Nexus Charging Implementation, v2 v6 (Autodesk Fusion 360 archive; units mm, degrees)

design "Nexus Charging Implementation, v2" references "9401-0-15-15-23-27-10-0 - Connector One", "0436-0-15-15-03-27-10-0 - Connector Two v2"
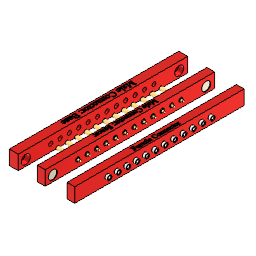
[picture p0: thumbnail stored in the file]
description: STEP AP214
part number: mill-max-0855
base_feature "Base Feature1" bodies "Pin 1"
copy_paste_bodies "CopyPasteBodies1" bodies "Pin Cover"
move "Move1"
sketch "Sketch1" plane through (0, 0, 0) normal (1, 0, 0) x axis (0, 1, 0)
  line L1 (-2.1437, -2.54) -> (6.35, -2.54)
  line L2 (-2.1437, 2.4142) -> (-2.1437, -2.54)
  line L3 (6.35, 2.4142) -> (-2.1437, 2.4142)
  line L4 (6.35, -2.54) -> (6.35, 2.4142)
  circle C1 centre (0, 0) radius 1.27
  circle C2 centre (0, 0) radius 1.27
  circle C3 centre (0, 0) radius 1.5151
  point P1 (0, 0)
  point P6 (0, 0)
  point P8 (0, 0)
  horizontal L1
  vertical L2
  horizontal L3
  vertical L4
  coincident P1 P6
  concentric C1 C2
  coincident P1 P8
extrude "Extrude1" new body sketch "Sketch1" profile of C1 C2 C3 against normal blind 4.826 and along normal blind 1.524 bodies "Pin Cover 1", "Pin Cover"
extrude "Extrude2" new body sketch "Sketch1" profile of L1 L2 L3 L4 C3 along normal blind 1.27 bodies "Connecting Pins", "Pin Cover"
copy_paste_bodies "CopyPasteBodies2" bodies "Pin Cover"
move "Move2"
move "Move3"
sketch "Circle Magnet" plane through (0, 0, 0) normal (1, 0, 0) x axis (0, 1, 0)
  circle C1 centre (0, 0) radius 3.175
  point P1 (0, 0)
  point P2 (0, 0)
  coincident P1 P2
  dimension "d7" diameter C1 = 6.35
extrude "Extrude3" new body sketch "Circle Magnet" along normal blind 3.175 bodies "Magnet", "Pin Cover"
move "Move4"
copy_paste_bodies "CopyPasteBodies3" bodies "Pin Cover"
move "Move5"
copy_paste_bodies "CopyPasteBodies4" bodies "Pin Cover"
copy_paste_bodies "CopyPasteBodies5" bodies "Pin Cover"
move "Move6"
move "Move7"
copy_paste_bodies "CopyPasteBodies6"
move "Move8"
copy_paste_bodies "CopyPasteBodies7"
move "Move9"
copy_paste_bodies "CopyPasteBodies8"
move "Move10"
copy_paste_bodies "CopyPasteBodies9"
move "Move11"
move_face "MoveFace1"
move_face "MoveFace2"
move_face "MoveFace3"
move "Move12"
copy_paste_bodies "CopyPasteBodies10" bodies "Pin Cover"
move "Move13"
move "Move14"
move "Move15"
move "Move16"
move_face "MoveFace4"
move "Move17"
extrude "Extrude4" new body of existing geometry blind 69.85 bodies "Pin Cover"
sketch "Sketch3" plane through (0, 0, 0) normal (1, 0, 0) x axis (0, 1, 0)
sketch "Sketch4" plane through (0, 0, 0) normal (1, 0, 0) x axis (0, 1, 0)
  line L1 (-5.08, 5.08) -> (76.2, 5.08)
  line L2 (-5.08, -5.08) -> (-5.08, 5.08)
  line L3 (76.2, -5.08) -> (-5.08, -5.08)
  line L4 (76.2, 5.08) -> (76.2, -5.08)
  circle C1 centre (72.644, 0) radius 1.3746
  circle C2 centre (66.04, 0) radius 1.3678
  circle C3 centre (59.436, 0) radius 1.4235
  circle C4 centre (52.832, 0) radius 1.4502
  circle C5 centre (46.228, 0) radius 1.4235
  circle C6 centre (26.416, 0) radius 1.4235
  circle C7 centre (39.624, 0) radius 1.4235
  circle C8 centre (0, 0) radius 1.4502
  circle C9 centre (6.604, 0) radius 1.4235
  circle C10 centre (13.208, 0) radius 1.4235
  circle C11 centre (19.812, 0) radius 1.4502
  circle C12 centre (26.416, 0) radius 1.4235
  circle C13 centre (33.02, 0) radius 1.3678
  horizontal L1
  vertical L2
  horizontal L3
  vertical L4
extrude "Extrude5" new body sketch "Sketch4" against normal blind 7.62 bodies "Connector Big", "Pin Cover"
move "Move18"
extrude "Extrude6" cut of existing geometry blind -0.508
extrude "Extrude7" cut of existing geometry blind -1.016
extrude "Extrude8" new body of existing geometry blind 0.254 bodies "Connector Big Partial", "Pin Cover"
extrude "Extrude9" add of existing geometry blind 6.35 bodies "Connector Big Partial"
extrude "Extrude10" of existing geometry blind 10.16
extrude "Extrude11" new body of existing geometry blind 11.43 bodies "Pin Cover"
extrude "Extrude12" cut of existing geometry blind 2.54
extrude "Extrude13" cut of existing geometry blind -2.54
extrude "Extrude14" cut of existing geometry blind -1.016
extrude "Extrude15" add of existing geometry blind 0.762
copy_paste_bodies "CopyPasteBodies11" bodies "Pin Cover"
move "Move19"
extrude "Extrude16" add of existing geometry blind 8.89
extrude "Extrude17" add of existing geometry blind 0.254
extrude "Extrude18" add of existing geometry blind 0.254
component_insert "Component Insert1"
component_insert "Component Insert2"
copy_paste_bodies "CopyPasteBodies12" bodies "Pin Cover"
move "Move20"
position "Position1"
sketch "Sketch5" plane through (30.5751, 0, 0) normal (-1, 0, 0) x axis (0, -1, 0)
  circle C1 centre (0, 0) radius 1.016
  circle C2 centre (0, 0) radius 1.591
  concentric C1 C2
sketch "Sketch6" plane through (30.5751, 0, 0) normal (-1, 0, 0) x axis (0, -1, 0)
sketch "Female Charging Contact Sketch" plane through (30.5751, 0, 0) normal (-1, 0, 0) x axis (0, -1, 0)
  circle C1 centre (0, 0) radius 1.016
  circle C2 centre (0, 0) radius 1.2701
  circle C3 centre (0, 0) radius 1.754
  point P1 (0, 0)
  point P3 (0, 0)
  coincident P1 P3
  concentric C1 C3
extrude "Extrude19" new body sketch "Female Charging Contact Sketch" profile of C2 C3 against normal blind 5.588 bodies "Female Connector Spacer 1", "Pin Cover"
extrude "Extrude20" cut of existing geometry blind -2.54
extrude "Extrude21" add of existing geometry blind 1.27
move "Move21"
extrude "Extrude22" cut of existing geometry blind -2.1844
position "Position2"
component_insert "Component Insert3" bodies "Pin Cover"
copy_paste_bodies "CopyPasteBodies13"
move "Move22"
copy_paste_bodies "CopyPasteBodies14"
move "Move23"
copy_paste_bodies "CopyPasteBodies15"
move "Move24"
copy_paste_bodies "CopyPasteBodies16"
move "Move25"
component_insert "Component Insert4" bodies "Pin Cover"
component_insert "Component Insert6" bodies "Pin Cover"
component_insert "Component Insert7" bodies "Pin Cover"
component_insert "Component Insert8" bodies "Pin Cover"
component_insert "Component Insert9" bodies "Pin Cover"
component_insert "Component Insert10" bodies "Pin Cover"
component_insert "Component Insert11" bodies "Pin Cover"
component_insert "Component Insert12" bodies "Pin Cover"
component_insert "Component Insert13" bodies "Pin Cover"
position "Position3"
component_insert "Component Insert14" bodies "Pin Cover"
copy_paste_bodies "CopyPasteBodies17"
move "Move26"
extrude "Extrude23" add of existing geometry blind 1.3462
extrude "Extrude24" add of existing geometry blind 0.1524 bodies "Connector Big Female End (1)", "Female Connector Spacer 2", "Female Connector Spacer 3", "Female Connector Spacer 6", "Female Connector Spacer 5", "Female Connector Spacer 4", "Female Connector Spacer 7", "Female Connector Spacer 8"
sketch "Sketch8" plane through (7.7978, 0, 0) normal (1, 0, 0) x axis (0, 1, 0)
  line L1 (-22.86, 5.08) -> (96.52, 5.08)
  line L2 (-22.86, -5.08) -> (-22.86, 5.08)
  line L3 (85.09, -5.08) -> (-22.86, -5.08)
  line L4 (96.52, -5.08) -> (85.09, -5.08)
  line L5 (96.52, 5.08) -> (96.52, -5.08)
  circle C1 centre (0, 0) radius 1.4502
  circle C2 centre (13.208, 0) radius 1.4235
  circle C3 centre (33.02, 0) radius 1.3678
  circle C4 centre (19.812, 0) radius 1.4502
  circle C5 centre (39.624, 0) radius 1.4235
  circle C6 centre (26.416, 0) radius 1.4235
  circle C7 centre (59.436, 0) radius 1.4235
  circle C8 centre (66.04, 0) radius 1.3678
  circle C9 centre (6.604, 0) radius 1.4235
  circle C10 centre (52.832, 0) radius 1.4502
  circle C11 centre (72.644, 0) radius 1.3746
  circle C12 centre (46.228, 0) radius 1.4235
move "Move27"
move "Move28"
move "Move29"
move "Move30"
move "Move31"
sketch "Sketch9" plane through (0, 0, 0) normal (1, 0, 0) x axis (0, 1, 0)
  line L1 (-22.86, 5.0799) -> (96.52, 5.0799)
  line L2 (-22.86, -5.0801) -> (-22.86, 5.0799)
  line L3 (96.52, -5.0801) -> (-22.86, -5.0801)
  line L4 (96.52, 5.0799) -> (96.52, -5.0801)
  point P4 (-22.86, -5.0801)
  point P7 (-22.86, -5.0801)
  point P2 (96.52, 5.0799)
  point P6 (96.52, 5.0799)
  horizontal L1
  vertical L2
  horizontal L3
  vertical L4
  coincident P4 P7
  coincident P2 P6
extrude "Extrude25" new body sketch "Sketch9" against normal blind 0.762 bodies "Connector Big Male Tip Added part", "Pin Cover"
copy_paste_bodies "CopyPasteBodies18"
move "Move32"
extrude "Extrude26" cut of existing geometry blind -0.0508
sketch "Sketch10" plane through (0, 0, 5.08) normal (0, 0, 1) x axis (-1, 0, 0)
  dimension "d56" = 3.81
  dimension "d60" = 3.048
extrude "Extrude27" cut sketch "Sketch10" against normal blind 0.508
extrude "Extrude28" cut sketch "Sketch10" against normal blind 0.762
sketch "Sketch11" plane through (0, 0, 5.0799) normal (0, 0, 1) x axis (-1, 0, 0)
  dimension "d64" = 3.048
extrude "Extrude29" cut sketch "Sketch11" against normal blind 0.508
move "Move33"
move "Move34"
move "Move35"
move "Move36"
move "Move37"
move_face "MoveFace5"
move_face "MoveFace6"
extrude "Extrude30" cut of existing geometry blind 0.762
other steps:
base_feature "Base Feature2" bodies "Pin 2", "Pin Cover"
base_feature "Base Feature3" bodies "SPACER", "Pin Cover"
base_feature "Base Feature4" bodies "Pin Cover", "Pin Cover 2"
base_feature "Base Feature5" bodies "Pin Cover (1)", "Pin Cover 3", "Pin Cover"
base_feature "Base Feature6" bodies "Pin 3", "Pin Cover"
base_feature "Base Feature7" bodies "Pin 3", "Pin Cover 3", "Pin 4", "Pin Cover 4", "Pin Cover"
base_feature "Base Feature8" bodies "Pin 3 (1)", "Pin 3 (1) (1)", "Pin Cover 3 (1)", "Pin Cover 3 (1) (1)", "Pin 5", "Pin 6", "Pin Cover 5", "Pin Cover 6"
base_feature "Base Feature9" bodies "Pin 3 (1) (2)", "Pin 3 (1) (1) (1)", "Pin Cover 3 (1) (2)", "Pin Cover 3 (1) (1) (1)", "Pin Cover 3 (1) (1) (2)", "Pin 3 (1) (1) (1) (1)", "Pin 7", "Pin 8"
base_feature "Base Feature10" bodies "Pin Cover 3 (1) (1) (1) (1)", "Pin 3 (1) (2) (1)", "Pin Cover 3 (1) (1) (2) (1)", "Pin 3 (1) (1) (1) (1) (1)", "Pin Cover 3 (1) (2) (1)", "Pin 3 (1) (1) (1) (1) (2)", "Pin Cover 12", "Pin 10"
base_feature "Base Feature11" bodies "Magnet", "Magnet (1)", "Pin Cover"
base_feature "Base Feature12" bodies "Pin Cover"
base_feature "Base Feature13" bodies "Connector Big", "Connector Big Male Tip", "Pin Cover"
base_feature "Base Feature14" bodies "Female Connector Spacer 2", "Pin Cover"
base_feature "Base Feature15" bodies "Female Connector Spacer 2", "Female Connector Spacer 3", "Pin Cover"
base_feature "Base Feature16" bodies "Female Connector Spacer 3", "Female Connector Spacer 2 (1)", "Female Connector Spacer 1", "Female Connector Spacer 6", "Female Connector Spacer 5", "Female Connector Spacer 4", "Pin Cover"
base_feature "Base Feature17" bodies "Female Connector Spacer 1 (1)", "Female Connector Spacer 2 (2)", "Female Connector Spacer 4", "Female Connector Spacer 6", "Female Connector Spacer 3 (1)", "Female Connector Spacer 5", "Female Connector Spacer 7", "Female Connector Spacer 8"
base_feature "Base Feature18" bodies "Connector Big Female End", "Connector Big Female End (1)", "Pin Cover"
base_feature "Base Feature19" bodies "Connector Big Male Tip", "Connector Big Male Tip (1)", "Pin Cover"
named bodies: "Pin 1", "Pin 2", "Pin Cover 1", "Connecting Pins", "SPACER", "Magnet", "Pin Cover", "Pin Cover 2", "Pin Cover (1)", "Pin Cover 3", "Pin 3", "Pin 4", "Pin Cover 4", "Pin 3 (1)", "Pin 3 (1) (1)", "Pin Cover 3 (1)", "Pin Cover 3 (1) (1)", "Pin 5", "Pin 6", "Pin Cover 5", "Pin Cover 6", "Pin 3 (1) (2)", "Pin 3 (1) (1) (1)", "Pin Cover 3 (1) (2)", "Pin Cover 3 (1) (1) (1)", "Pin Cover 3 (1) (1) (2)", "Pin 3 (1) (1) (1) (1)", "Pin 7", "Pin 8", "Pin Cover 7", "Pin Cover 9", "Pin Cover 8", "Pin 9", "Pin Cover 3 (1) (1) (1) (1)", "Pin 3 (1) (2) (1)", "Pin Cover 3 (1) (1) (2) (1)", "Pin 3 (1) (1) (1) (1) (1)", "Pin Cover 3 (1) (2) (1)", "Pin 3 (1) (1) (1) (1) (2)", "Pin Cover 12", "Pin 10", "Pin Cover 11", "Pin  12", "Pin Cover 10", "Pin 11", "Magnet (1)", "Connector Big", "Connector Big Partial", "Connector Big Male Tip", "Female Connector Spacer 1", "Female Connector Spacer 2", "Female Connector Spacer 3", "Female Connector Spacer 2 (1)", "Female Connector Spacer 6", "Female Connector Spacer 5", "Female Connector Spacer 4", "Female Connector Spacer 1 (1)", "Female Connector Spacer 2 (2)", "Female Connector Spacer 3 (1)", "Female Connector Spacer 7"

design "0436-0-15-15-03-27-10-0 - Connector Two v2"
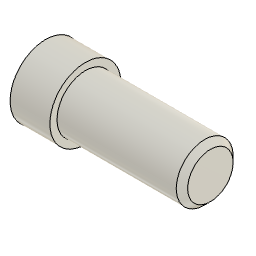
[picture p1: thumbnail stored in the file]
description: STEP AP214
part number: 0436-0-15-15-03-27-10-0
base_feature "Base Feature" bodies "0436-0-15-15-03-27-10-0"
named bodies: "0436-0-15-15-03-27-10-0"

design "9401-0-15-15-23-27-10-0 - Connector One"
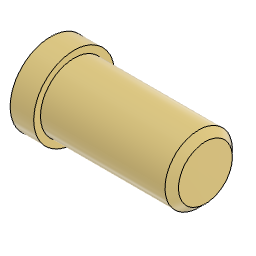
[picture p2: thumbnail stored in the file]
description: STEP AP214
base_feature "Base Feature" bodies "9401-0-15-15-23-27-10-0"
named bodies: "9401-0-15-15-23-27-10-0"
